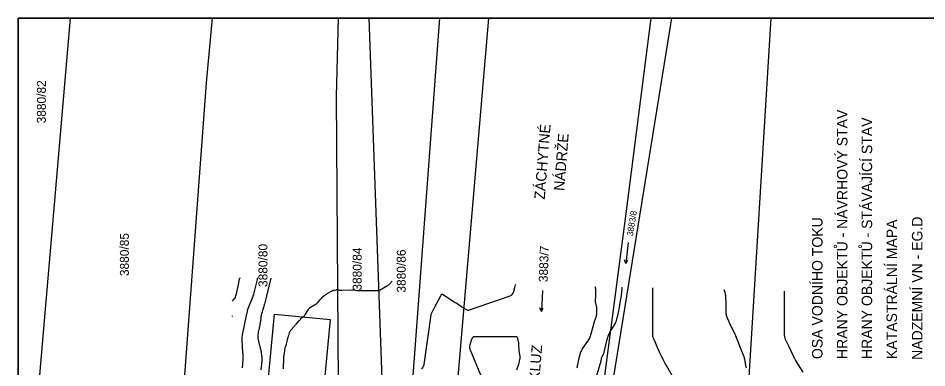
# Model space of a CAD drawing. Extents: x -534410 to -534262, y -1190162 to -1189584.
# Drawn here: x -534410.1 to -534323.5, y -1189617.8 to -1189584.5 of the extents above; entities that cross this region are included whole.
import ezdxf

# ---------------------------------------------------------------- set-up
doc = ezdxf.new("R2010")
doc.units = 0
for name, color, linetype in [('30', 7, 'Continuous'), ('31', 7, 'Continuous'), ('_N_text', 7, 'Continuous'), ('_přístup', 7, 'Continuous'), ('_rámeček', 7, 'Continuous'), ('_rámeček_mřížka', 7, 'Continuous'), ('Hranice parcel', 7, 'Continuous'), ('LEGENDA', 7, 'Continuous'), ('Parcelní čísla', 7, 'Continuous'), ('Značky kultur', 7, 'Continuous')]:
    doc.layers.add(name, color=color, linetype=linetype)

msp = doc.modelspace()

# ---------------------------------------------------------------- linework, layer by layer
at = {"layer": '30'}
for points in [[(-534389.699, -1189611.439), (-534389.49, -1189611.211), (-534389.465, -1189611.181), (-534389.443, -1189611.148), (-534389.426, -1189611.113), (-534389.412, -1189611.075), (-534389.366, -1189610.921), (-534389.354, -1189610.883), (-534389.343, -1189610.844), (-534389.333, -1189610.805), (-534389.323, -1189610.766), (-534389.245, -1189610.447), (-534389.229, -1189610.38), (-534389.214, -1189610.314), (-534389.2, -1189610.247), (-534389.187, -1189610.18), (-534389.097, -1189609.697), (-534389.079, -1189609.611), (-534389.06, -1189609.525), (-534389.039, -1189609.439), (-534389.016, -1189609.354), (-534388.967, -1189609.181)], [(-534386.02, -1189609.256), (-534386.253, -1189610.164), (-534386.27, -1189610.232), (-534386.288, -1189610.3), (-534386.305, -1189610.368), (-534386.322, -1189610.436), (-534386.389, -1189610.708), (-534386.406, -1189610.776), (-534386.423, -1189610.844), (-534386.441, -1189610.912), (-534386.458, -1189610.981), (-534386.646, -1189611.72), (-534386.65, -1189611.739), (-534386.655, -1189611.757), (-534386.658, -1189611.775), (-534386.662, -1189611.794), (-534386.675, -1189611.868), (-534386.679, -1189611.887), (-534386.683, -1189611.905), (-534386.688, -1189611.924), (-534386.693, -1189611.942), (-534386.923, -1189612.678), (-534386.947, -1189612.762), (-534386.967, -1189612.846), (-534386.982, -1189612.931), (-534386.994, -1189613.018), (-534387.032, -1189613.364), (-534387.042, -1189613.45), (-534387.055, -1189613.536), (-534387.07, -1189613.622), (-534387.088, -1189613.707), (-534387.193, -1189614.194), (-534387.207, -1189614.259), (-534387.219, -1189614.323), (-534387.229, -1189614.388), (-534387.239, -1189614.453), (-534387.273, -1189614.714), (-534387.279, -1189614.779), (-534387.28, -1189614.844), (-534387.276, -1189614.909), (-534387.267, -1189614.974), (-534387.217, -1189615.258), (-534387.204, -1189615.327), (-534387.189, -1189615.395), (-534387.172, -1189615.463), (-534387.155, -1189615.53), (-534387.046, -1189615.923), (-534387.023, -1189616.011), (-534387.003, -1189616.1), (-534386.986, -1189616.189), (-534386.971, -1189616.279), (-534386.918, -1189616.658), (-534386.907, -1189616.751), (-534386.901, -1189616.845), (-534386.9, -1189616.939), (-534386.904, -1189617.033), (-534386.935, -1189617.534), (-534386.938, -1189617.59), (-534386.943, -1189617.646), (-534386.948, -1189617.702), (-534386.954, -1189617.758), (-534386.98, -1189617.983)], [(-534371.678, -1189617.855), (-534371.557, -1189617.776), (-534371.474, -1189617.657), (-534371.429, -1189617.499), (-534370.747, -1189612.756), (-534370.735, -1189612.688), (-534370.716, -1189612.622), (-534370.692, -1189612.557), (-534370.662, -1189612.494), (-534370.53, -1189612.247), (-534370.497, -1189612.185), (-534370.464, -1189612.124), (-534370.431, -1189612.062), (-534370.398, -1189612), (-534369.825, -1189610.935), (-534369.806, -1189610.899), (-534369.778, -1189610.847), (-534369.774, -1189610.839), (-534369.749, -1189610.787), (-534369.745, -1189610.782), (-534369.741, -1189610.778), (-534369.736, -1189610.777), (-534369.73, -1189610.778), (-534369.7, -1189610.784), (-534369.693, -1189610.786), (-534369.686, -1189610.788), (-534369.679, -1189610.791), (-534369.673, -1189610.795), (-534368.641, -1189611.443), (-534368.55, -1189611.502), (-534368.459, -1189611.561), (-534368.368, -1189611.621), (-534368.279, -1189611.682), (-534367.863, -1189611.97), (-534367.803, -1189612.01), (-534367.741, -1189612.049), (-534367.679, -1189612.087), (-534367.616, -1189612.123), (-534367.361, -1189612.265), (-534367.297, -1189612.293), (-534367.231, -1189612.306), (-534367.165, -1189612.304), (-534367.096, -1189612.287), (-534363.204, -1189610.926), (-534363.098, -1189610.876), (-534363.012, -1189610.806), (-534362.946, -1189610.717), (-534362.901, -1189610.608), (-534362.76, -1189610.135), (-534362.725, -1189610.016), (-534362.691, -1189609.898), (-534362.678, -1189609.85)], [(-534355.152, -1189610.042), (-534355.122, -1189610.107), (-534355.096, -1189610.184), (-534355.08, -1189610.263), (-534355.073, -1189610.345), (-534355.065, -1189610.688), (-534355.064, -1189610.766), (-534355.066, -1189610.844), (-534355.07, -1189610.922), (-534355.076, -1189611), (-534355.106, -1189611.313), (-534355.11, -1189611.39), (-534355.107, -1189611.466), (-534355.098, -1189611.541), (-534355.081, -1189611.616), (-534355.002, -1189611.915), (-534354.986, -1189611.99), (-534354.975, -1189612.066), (-534354.97, -1189612.142), (-534354.97, -1189612.219), (-534354.993, -1189612.699), (-534355, -1189612.771), (-534355.011, -1189612.843), (-534355.027, -1189612.913), (-534355.048, -1189612.982), (-534355.144, -1189613.258), (-534355.167, -1189613.327), (-534355.189, -1189613.397), (-534355.211, -1189613.467), (-534355.231, -1189613.537), (-534355.527, -1189614.592), (-534355.534, -1189614.617), (-534355.542, -1189614.643), (-534355.549, -1189614.668), (-534355.557, -1189614.693), (-534355.597, -1189614.819), (-534355.601, -1189614.832), (-534355.605, -1189614.844), (-534355.609, -1189614.857), (-534355.614, -1189614.87), (-534355.631, -1189614.922), (-534355.636, -1189614.934), (-534355.641, -1189614.947), (-534355.647, -1189614.959), (-534355.654, -1189614.971), (-534355.717, -1189615.084), (-534355.73, -1189615.106), (-534355.744, -1189615.129), (-534355.758, -1189615.151), (-534355.773, -1189615.172), (-534356.336, -1189615.998), (-534356.384, -1189616.075), (-534356.427, -1189616.154), (-534356.464, -1189616.237), (-534356.496, -1189616.323), (-534356.61, -1189616.671), (-534356.637, -1189616.758), (-534356.661, -1189616.846), (-534356.682, -1189616.935), (-534356.701, -1189617.024), (-534356.794, -1189617.517), (-534356.815, -1189617.627), (-534356.836, -1189617.737), (-534356.857, -1189617.846)], [(-534347.767, -1189618.539), (-534348.289, -1189617.635), (-534348.333, -1189617.557), (-534348.377, -1189617.479), (-534348.42, -1189617.4), (-534348.462, -1189617.321), (-534348.629, -1189617.003), (-534348.671, -1189616.924), (-534348.711, -1189616.844), (-534348.751, -1189616.763), (-534348.79, -1189616.682), (-534348.96, -1189616.319), (-534349.001, -1189616.231), (-534349.041, -1189616.143), (-534349.08, -1189616.055), (-534349.119, -1189615.966), (-534349.464, -1189615.159), (-534349.478, -1189615.128), (-534349.492, -1189615.096), (-534349.506, -1189615.065), (-534349.52, -1189615.033), (-534349.575, -1189614.907), (-534349.588, -1189614.876), (-534349.596, -1189614.843), (-534349.602, -1189614.81), (-534349.603, -1189614.776), (-534349.603, -1189610.183)], [(-534337.085, -1189610.502), (-534337.085, -1189614.593), (-534337.078, -1189614.717), (-534337.058, -1189614.838), (-534337.024, -1189614.957), (-534336.977, -1189615.072), (-534336.655, -1189615.756), (-534336.459, -1189616.173), (-534336.174, -1189616.778), (-534336.158, -1189616.811), (-534336.141, -1189616.844), (-534336.125, -1189616.877), (-534336.108, -1189616.91), (-534336.039, -1189617.04), (-534336.021, -1189617.073), (-534336.003, -1189617.105), (-534335.984, -1189617.137), (-534335.965, -1189617.168), (-534335.305, -1189618.224)], [(-534389.686, -1189612.902), (-534389.675, -1189612.845)], [(-534362.584, -1189617.989), (-534362.442, -1189617.621), (-534362.419, -1189617.557), (-534362.398, -1189617.493), (-534362.379, -1189617.428), (-534362.363, -1189617.363), (-534362.28, -1189616.994), (-534362.267, -1189616.919), (-534362.261, -1189616.844), (-534362.263, -1189616.769), (-534362.272, -1189616.693), (-534362.323, -1189616.39), (-534362.335, -1189616.314), (-534362.344, -1189616.238), (-534362.351, -1189616.162), (-534362.355, -1189616.085), (-534362.373, -1189615.644), (-534362.378, -1189615.563), (-534362.387, -1189615.482), (-534362.4, -1189615.402), (-534362.417, -1189615.322), (-534362.491, -1189615.004), (-534362.517, -1189614.934), (-534362.56, -1189614.884), (-534362.618, -1189614.854), (-534362.691, -1189614.845), (-534366.559, -1189614.845), (-534366.68, -1189614.86), (-534366.777, -1189614.908), (-534366.851, -1189614.986), (-534366.902, -1189615.097), (-534367.06, -1189615.601), (-534367.088, -1189615.727), (-534367.093, -1189615.851), (-534367.076, -1189615.975), (-534367.036, -1189616.097), (-534365.664, -1189619.379)]]:
    msp.add_lwpolyline(points, dxfattribs=at)
at = {"layer": '31'}
for points in [[(-534387.304, -1189609.223), (-534387.316, -1189609.271), (-534387.329, -1189609.325), (-534387.342, -1189609.378), (-534387.681, -1189610.772), (-534387.689, -1189610.801), (-534387.7, -1189610.849), (-534387.706, -1189610.871), (-534387.708, -1189610.879), (-534387.711, -1189610.888), (-534387.739, -1189610.959), (-534387.752, -1189610.993), (-534388.222, -1189612.19), (-534388.245, -1189612.254), (-534388.267, -1189612.318), (-534388.286, -1189612.383), (-534388.302, -1189612.448), (-534388.364, -1189612.712), (-534388.379, -1189612.779), (-534388.394, -1189612.845), (-534388.408, -1189612.911), (-534388.422, -1189612.977), (-534388.544, -1189613.584), (-534388.552, -1189613.623), (-534388.559, -1189613.662), (-534388.567, -1189613.701), (-534388.573, -1189613.74), (-534388.6, -1189613.896), (-534388.607, -1189613.936), (-534388.614, -1189613.975), (-534388.622, -1189614.013), (-534388.63, -1189614.052), (-534388.756, -1189614.627), (-534388.777, -1189614.736), (-534388.789, -1189614.846), (-534388.795, -1189614.956), (-534388.793, -1189615.067), (-534388.755, -1189615.826), (-534388.755, -1189615.833), (-534388.756, -1189615.84), (-534388.758, -1189615.854), (-534388.759, -1189615.861), (-534388.759, -1189615.867), (-534388.701, -1189616.599), (-534388.694, -1189616.722), (-534388.692, -1189616.844), (-534388.694, -1189616.967), (-534388.702, -1189617.09), (-534388.76, -1189617.818)], [(-534374.468, -1189609.55), (-534374.482, -1189609.568), (-534374.514, -1189609.607), (-534374.547, -1189609.645), (-534374.581, -1189609.682), (-534374.616, -1189609.718), (-534374.759, -1189609.86), (-534374.796, -1189609.895), (-534374.834, -1189609.927), (-534374.875, -1189609.956), (-534374.917, -1189609.983), (-534375.663, -1189610.429), (-534375.704, -1189610.449), (-534375.746, -1189610.464), (-534375.791, -1189610.473), (-534375.837, -1189610.475), (-534376.024, -1189610.471), (-534376.071, -1189610.47), (-534376.118, -1189610.47), (-534376.165, -1189610.469), (-534376.212, -1189610.469), (-534377.274, -1189610.469), (-534377.321, -1189610.469), (-534377.368, -1189610.469), (-534377.415, -1189610.468), (-534377.462, -1189610.467), (-534377.649, -1189610.464), (-534377.696, -1189610.462), (-534377.743, -1189610.459), (-534377.789, -1189610.454), (-534377.836, -1189610.449), (-534378.078, -1189610.414), (-534378.133, -1189610.408), (-534378.189, -1189610.404), (-534378.245, -1189610.402), (-534378.301, -1189610.404), (-534379.247, -1189610.445), (-534379.297, -1189610.446), (-534379.348, -1189610.443), (-534379.397, -1189610.437), (-534379.447, -1189610.428), (-534379.644, -1189610.384), (-534379.694, -1189610.376), (-534379.743, -1189610.374), (-534379.792, -1189610.376), (-534379.842, -1189610.385), (-534380.039, -1189610.428), (-534380.088, -1189610.441), (-534380.135, -1189610.457), (-534380.181, -1189610.477), (-534380.225, -1189610.5), (-534380.693, -1189610.765), (-534380.761, -1189610.806), (-534380.828, -1189610.851), (-534380.892, -1189610.9), (-534380.953, -1189610.952), (-534381.194, -1189611.166), (-534381.253, -1189611.22), (-534381.311, -1189611.277), (-534381.367, -1189611.334), (-534381.422, -1189611.394), (-534381.636, -1189611.635), (-534381.692, -1189611.692), (-534381.751, -1189611.745), (-534381.815, -1189611.792), (-534381.883, -1189611.835), (-534382.263, -1189612.052), (-534382.345, -1189612.106), (-534382.418, -1189612.17), (-534382.482, -1189612.242), (-534382.536, -1189612.324), (-534382.753, -1189612.704), (-534382.795, -1189612.772), (-534382.843, -1189612.836), (-534382.895, -1189612.896), (-534382.953, -1189612.952), (-534383.194, -1189613.166), (-534383.253, -1189613.22), (-534383.311, -1189613.277), (-534383.367, -1189613.334), (-534383.422, -1189613.394), (-534383.636, -1189613.635), (-534383.689, -1189613.695), (-534383.742, -1189613.756), (-534383.793, -1189613.818), (-534383.844, -1189613.881), (-534384.149, -1189614.258), (-534384.187, -1189614.309), (-534384.22, -1189614.364), (-534384.248, -1189614.42), (-534384.272, -1189614.48), (-534384.356, -1189614.723), (-534384.377, -1189614.784), (-534384.396, -1189614.845), (-534384.414, -1189614.907), (-534384.431, -1189614.969), (-534384.614, -1189615.683), (-534384.62, -1189615.705), (-534384.627, -1189615.726), (-534384.635, -1189615.746), (-534384.644, -1189615.766), (-534384.682, -1189615.846), (-534384.691, -1189615.867), (-534384.698, -1189615.887), (-534384.703, -1189615.909), (-534384.707, -1189615.93), (-534384.804, -1189616.624), (-534384.818, -1189616.734), (-534384.828, -1189616.845), (-534384.835, -1189616.956), (-534384.839, -1189617.067), (-534384.85, -1189617.68), (-534384.851, -1189617.708), (-534384.852, -1189617.736), (-534384.852, -1189617.764), (-534384.853, -1189617.792), (-534384.858, -1189617.905)], [(-534355.155, -1189619.148), (-534354.596, -1189617.363), (-534354.581, -1189617.313), (-534354.569, -1189617.261), (-534354.558, -1189617.21), (-534354.549, -1189617.158), (-534354.516, -1189616.949), (-534354.506, -1189616.897), (-534354.493, -1189616.847), (-534354.476, -1189616.797), (-534354.455, -1189616.749), (-534354.316, -1189616.461), (-534354.287, -1189616.396), (-534354.262, -1189616.331), (-534354.24, -1189616.264), (-534354.222, -1189616.195), (-534353.962, -1189615.104), (-534353.955, -1189615.077), (-534353.948, -1189615.051), (-534353.94, -1189615.025), (-534353.932, -1189614.999), (-534353.887, -1189614.87), (-534353.883, -1189614.857), (-534353.878, -1189614.844), (-534353.874, -1189614.832), (-534353.87, -1189614.819), (-534353.854, -1189614.767), (-534353.85, -1189614.755), (-534353.846, -1189614.742), (-534353.841, -1189614.729), (-534353.836, -1189614.717), (-534353.769, -1189614.538), (-534353.755, -1189614.504), (-534353.74, -1189614.471), (-534353.723, -1189614.439), (-534353.705, -1189614.408), (-534353.208, -1189613.6), (-534353.169, -1189613.531), (-534353.134, -1189613.459), (-534353.106, -1189613.385), (-534353.082, -1189613.309), (-534352.999, -1189612.999), (-534352.978, -1189612.922), (-534352.959, -1189612.844), (-534352.941, -1189612.766), (-534352.925, -1189612.687), (-534352.756, -1189611.86), (-534352.753, -1189611.852), (-534352.75, -1189611.841), (-534352.748, -1189611.834), (-534352.624, -1189611.039), (-534352.61, -1189610.942), (-534352.597, -1189610.844), (-534352.586, -1189610.746), (-534352.577, -1189610.648), (-534352.537, -1189610.169), (-534352.533, -1189610.114), (-534352.533, -1189610.108)], [(-534340.673, -1189617.816), (-534340.684, -1189617.788), (-534340.693, -1189617.759), (-534340.7, -1189617.73), (-534340.84, -1189617.009), (-534340.858, -1189616.927), (-534340.879, -1189616.847), (-534340.905, -1189616.767), (-534340.934, -1189616.689), (-534341.059, -1189616.378), (-534341.09, -1189616.301), (-534341.121, -1189616.223), (-534341.153, -1189616.145), (-534341.184, -1189616.067), (-534341.609, -1189615.004), (-534341.617, -1189614.983), (-534341.625, -1189614.961), (-534341.633, -1189614.94), (-534341.641, -1189614.918), (-534341.675, -1189614.818), (-534341.681, -1189614.803), (-534341.687, -1189614.787), (-534341.693, -1189614.772), (-534341.7, -1189614.757), (-534341.736, -1189614.683), (-534341.758, -1189614.638), (-534342.267, -1189613.586), (-534342.302, -1189613.513), (-534342.337, -1189613.439), (-534342.371, -1189613.365), (-534342.404, -1189613.291), (-534342.536, -1189612.993), (-534342.566, -1189612.918), (-534342.587, -1189612.841), (-534342.601, -1189612.762), (-534342.607, -1189612.682), (-534342.628, -1189612.015), (-534342.629, -1189611.986), (-534342.629, -1189611.958), (-534342.629, -1189611.93), (-534342.63, -1189611.901), (-534342.63, -1189611.788), (-534342.63, -1189611.759), (-534342.63, -1189611.731), (-534342.631, -1189611.703), (-534342.631, -1189611.674), (-534342.651, -1189611.061), (-534342.658, -1189610.953), (-534342.672, -1189610.847), (-534342.694, -1189610.742), (-534342.722, -1189610.637), (-534342.81, -1189610.356)]]:
    msp.add_lwpolyline(points, dxfattribs=at)
at = {"layer": '_přístup'}
msp.add_lwpolyline([(-534387.143, -1189628.143), (-534385.688, -1189612.702), (-534380.389, -1189613.202), (-534381.845, -1189628.642)], close=True, dxfattribs=at)
at = {"layer": '_rámeček'}
for p, q in [((-534410.126, -1189584.47), (-534410.126, -1190161.97)), ((-534261.626, -1189584.47), (-534410.126, -1189584.47))]:
    msp.add_line(p, q, dxfattribs=at)
msp.add_lwpolyline([(-534410.126, -1189584.47), (-534261.626, -1189584.47), (-534261.626, -1189689.47), (-534410.126, -1189689.47)], close=True, dxfattribs=at)
at = {"layer": '_rámeček_mřížka'}
for p, q in [((-534410.126, -1189584.47), (-534410.126, -1190161.97)), ((-534261.626, -1189584.47), (-534410.126, -1189584.47))]:
    msp.add_line(p, q, dxfattribs=at)
at = {"layer": 'Hranice parcel'}
for points in [[(-534408.99, -1189627.6), (-534408.6, -1189624.8), (-534405.151, -1189584.47)], [(-534391.623, -1189584.47), (-534392.21, -1189590.63), (-534395.28, -1189632.21)], [(-534379.46, -1189637.54), (-534379.76, -1189591.95), (-534379.572, -1189584.47)], [(-534374.7, -1189639.14), (-534376.664, -1189584.47)], [(-534369.94, -1189584.47), (-534373, -1189625.37), (-534374.52, -1189639.2)], [(-534368.76, -1189625.38), (-534365.237, -1189584.47)], [(-534356.61, -1189636.93), (-534352.14, -1189603.1), (-534349.757, -1189584.47)], [(-534347.83, -1189584.47), (-534354.43, -1189625.3), (-534356.61, -1189636.93)], [(-534347.07, -1189935.15), (-534347.12, -1189900.1), (-534346.3, -1189826.77), (-534344.77, -1189736.43), (-534342.85, -1189658.07), (-534338.334, -1189584.47)]]:
    msp.add_lwpolyline(points, dxfattribs=at)
at = {"layer": 'Značky kultur'}
for p, q in [((-534351.951, -1189605.848), (-534352.196, -1189607.843)), ((-534352.196, -1189607.843), (-534352.323, -1189607.498)), ((-534352.196, -1189607.843), (-534351.99, -1189607.539)), ((-534360.134, -1189610.423), (-534360.239, -1189612.43)), ((-534360.239, -1189612.43), (-534360.39, -1189612.095)), ((-534360.239, -1189612.43), (-534360.054, -1189612.112))]:
    msp.add_line(p, q, dxfattribs=at)

# ---------------------------------------------------------------- texts
at = {"layer": '_N_text'}
for s, p in [('ZÁCHYTNÉ ', (-534359.92, -1189601.79)), ('NÁDRŽE', (-534358.064, -1189600.966)), ('SKLUZ', (-534360.496, -1189619.962))]:
    msp.add_text(s, height=1, rotation=85.46265, dxfattribs=at).set_placement(p)
at = {"layer": 'LEGENDA'}
for s, p in [('HRANY OBJEKTŮ - NÁVRHOVÝ STAV', (-534331.052, -1189616.969)), ('HRANY OBJEKTŮ - STÁVAJÍCÍ STAV', (-534328.698, -1189616.969)), ('OSA VODNÍHO TOKU', (-534333.43, -1189616.969)), ('KATASTRÁLNÍ MAPA', (-534326.328, -1189616.969)), ('NADZEMNÍ VN - EG.D', (-534323.904, -1189617.05))]:
    msp.add_text(s, height=1, rotation=89.99985, dxfattribs=at).set_placement(p)
at = {"layer": 'Parcelní čísla'}
for s, height, rotation, p in [('3880/82', 0.85, 90, (-534407.488, -1189594.499)), ('3883/8', 0.595, 81, (-534351.509, -1189605.288)), ('3880/85', 0.85, 90, (-534399.574, -1189609.061)), ('3880/80', 0.85, 90, (-534386.359, -1189610.098)), ('3880/84', 0.85, 90, (-534377.379, -1189610.445)), ('3883/7', 0.85, 88, (-534359.642, -1189609.647)), ('3880/86', 0.85, 90, (-534373.177, -1189610.633))]:
    msp.add_text(s, height=height, rotation=rotation, dxfattribs=at).set_placement(p)

doc.saveas('drawing.dxf')
